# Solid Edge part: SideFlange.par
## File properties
Author: ptcarter
Template: Ansimm.Par
Last saved by: ptcarter
Revision: 46
Application: Solid Edge
Accuracy: 0.99
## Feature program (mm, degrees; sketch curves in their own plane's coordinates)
sketch for "unnamed Protrusion 1" plane through (0, 0, 0) normal (0, 0, 1) x-axis (1, 0, 0)
  line (-45, -35) -> (-45, 35)
  arc centre (-35, 35) radius 10 from (-45, 35) to (-35, 45) cw
  line (-35, 45) -> (35, 45)
  arc centre (35, 35) radius 10 from (35, 45) to (45, 35) cw
  line (45, 35) -> (45, -35)
  arc centre (35, -35) radius 10 from (45, -35) to (35, -45) cw
  line (35, -45) -> (-35, -45)
  arc centre (-35, -35) radius 10 from (-35, -45) to (-45, -35) cw
extrude "unnamed Protrusion 1" add finite 10 along +normal
sketch for "Hole_1" plane through (0, 0, 10) normal (0, 0, 1) x-axis (1, 0, 0)
  hole centre (-35, -35) bore radius 5
hole "Hole_1" through
sketch for "Hole_2" plane through (0, 0, 10) normal (0, 0, 1) x-axis (1, 0, 0)
  hole centre (-35, 35) bore radius 5
hole "Hole_2" through
sketch for "Hole_3" plane through (0, 0, 10) normal (0, 0, 1) x-axis (1, 0, 0)
  hole centre (35, 35) bore radius 5
hole "Hole_3" through
sketch for "Hole_4" plane through (0, 0, 10) normal (0, 0, 1) x-axis (1, 0, 0)
  hole centre (35, -35) bore radius 5
hole "Hole_4" nominal diameter 7.8125 through
pattern "unnamed Pattern 1" of "Hole_1", "Hole_2", "Hole_3", "Hole_4"
sketch for "unnamed Protrusion 2" plane through (0, 0, 10) normal (0, 0, 1) x-axis (1, 0, 0)
  line (-17.3205, -30) -> (17.3205, -30)
  line (17.3205, -30) -> (34.641, 0)
  line (34.641, 0) -> (17.3205, 30)
  line (17.3205, 30) -> (-17.3205, 30)
  line (-17.3205, 30) -> (-34.641, 0)
  line (-34.641, 0) -> (-17.3205, -30)
extrude "unnamed Protrusion 2" add finite 20 along +normal
fillet "Round_1" radius 4
fillet "Round_2" radius 2  Radii2 = 1.5 mm
sketch for "Hole_5" plane through (0, 0, 30) normal (0, 0, 1) x-axis (1, 0, 0)
  hole centre (0, 0) bore radius 19
hole "Hole_5" through
sketch for "unnamed RevolvedCutout 1" plane through (0, 0, 0) normal (1, 0, 0) x-axis (0, 1, 0)
  line (25, 30) -> (28, 28.9081)
revolve "unnamed RevolvedCutout 1" cut full turn 360 deg
sketch for "unnamed RevolvedProtrusion 1" plane through (0, 0, 0) normal (0, -1, 0) x-axis (1, 0, 0)
revolve "unnamed RevolvedProtrusion 1" add full turn 360 deg about sketch line (0, -57.15) -> (0, -79.0482)
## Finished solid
Body 1: solid body, 56 faces, 118 edges, 60 vertices.
  Faces by surface: cylinder 28, plane 16, torus 10, cone 1, sphere 1
  Edges by curve: circle 62, line 44, intersection 12
Bounding box of the edges (mm; curved faces can reach further): 90.000 x 90.000 x 50.000, from (-45, -45, -20) to (45, 45, 30).
Cylindrical faces by radius (mm): R1.5 x6, R2 x4, R4 x6, R5 x4, R10 x4, R16 x1, R19 x1, R27.5 x1, R32.5 x1
Conical faces (half-angle, radius in mm at the cone's reference point): 70 deg R28 x1
Toroidal faces (ring radius, tube radius in mm): R5.5 r1.5 x6, R8 r2 x4
Spherical faces by radius (mm): R30 x1
Planar faces by outward normal: +x 1, +y 2, +z 3, -x 1, -y 2, -z 3, oblique 4
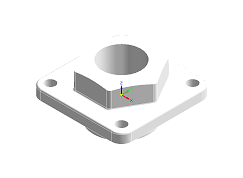
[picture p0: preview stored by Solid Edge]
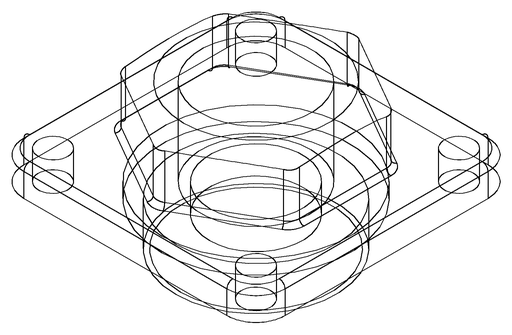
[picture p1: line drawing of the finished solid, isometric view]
